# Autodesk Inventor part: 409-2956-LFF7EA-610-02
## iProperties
Created: 2011-01
Part Number: 409-2956-LFF7EA-610-02
Cost Center: 0 lbmass
Material: A36 STEEL PLATE
Document SubType Name: Sheet Metal
Designer: S. Boerckel
Authority: 0 in^3
Mass: 5287.6 g
Surface Area: 1187.36 cm^2
Volume: 672.723 cm^3
Density: 7.86 g/cm^3
Flat Pattern Width: 17.78 cm
Flat Pattern Length: 40.1638 cm
Flat Pattern Area: 714.111 cm^2
Sheet Metal Rule: 1/2"Thk
Description: SIDE SUPPORT PLATE
SaveDate: 2008-01-15
SaveTime: 10:24
FileName: Sheet Metal
Wide: =<Flat Pattern Width>cm
Length: =<Flat Pattern Length>cm
Thickness: 0.5000 in
SMR: =<Sheet Metal Rule> - <Material>
Author: S. Boerckel
Revision Number: 0
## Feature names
1. Plate1
2. Plate3
3. Bend2
4. Cut1
